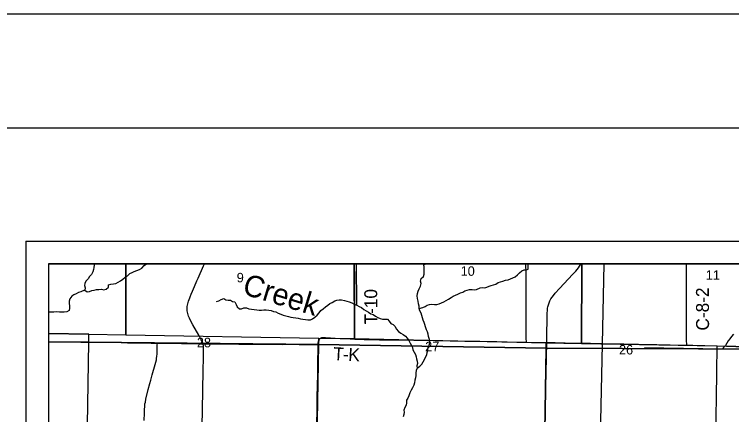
# Model space of a CAD drawing. Extents: x 0 to 42, y 0 to 22.
# Drawn here: x 1.949 to 5.107, y 20.235 to 22 of the extents above; entities that cross this region are included whole.
import ezdxf

# ---------------------------------------------------------------- set-up
doc = ezdxf.new("R2010")
doc.units = 0
for name, color, linetype in [('Default', 7, 'Continuous'), ('GM_X_County_Road', 7, 'Continuous'), ('GM_X_County_Road_Text', 7, 'Continuous'), ('GM_X_Interchange_Ramps', 7, 'Continuous'), ('GM_X_Minor_River', 7, 'Continuous'), ('GM_X_Minor_River_Text', 7, 'Continuous'), ('GM_X_Rail_Line', 7, 'Continuous'), ('GM_X_Section', 7, 'Continuous'), ('GM_X_Section_Text', 7, 'Continuous'), ('GM_X_State_Route', 7, 'Continuous'), ('GM_X_Township_Road', 7, 'Continuous'), ('GM_X_Township_Road_Text', 7, 'Continuous'), ('SH_Border', 7, 'Continuous'), ('SH_Cut_Line', 7, 'Continuous'), ('SH_Data', 7, 'Continuous')]:
    doc.layers.add(name, color=color, linetype=linetype)

msp = doc.modelspace()

# ---------------------------------------------------------------- linework, layer by layer
at = {"layer": 'Default'}
for points in [[(2.4394, 20.9), (2.1, 20.9), (2.1, 20.5927), (2.2765, 20.5898), (2.4394, 20.5869)], [(3.4456, 20.9), (2.4394, 20.9), (2.4394, 20.5869), (3.29, 20.5725), (3.4457, 20.5713)], [(4.4477, 20.9), (3.4456, 20.9), (3.4457, 20.5713), (4.2909, 20.5517), (4.4454, 20.5483)], [(5.4509, 20.9), (4.4477, 20.9), (4.4454, 20.5483), (5.2948, 20.5335), (5.4509, 20.5312)], [(2.1, 20.5927), (2.1, 20.5562), (2.2763, 20.5545), (2.2765, 20.5898)], [(2.1, 20.5562), (2.1, 19.5535), (2.2608, 19.5512), (2.2763, 20.5545)]]:
    msp.add_lwpolyline(points, close=True, dxfattribs=at)
at = {"layer": 'GM_X_County_Road'}
for points in [[(2.7794, 20.5478), (2.7784, 20.5512), (2.7761, 20.5571), (2.7721, 20.5656), (2.7613, 20.5848), (2.7353, 20.6308), (2.7249, 20.6499), (2.7194, 20.661), (2.7158, 20.6695), (2.7138, 20.6753), (2.7122, 20.6813), (2.711, 20.6873), (2.7101, 20.6934), (2.7097, 20.6995), (2.7097, 20.7057), (2.7101, 20.7118), (2.7108, 20.7179), (2.7122, 20.7239), (2.7157, 20.7359), (2.721, 20.7499), (2.7223, 20.7547), (2.7272, 20.7656), (2.7333, 20.7789), (2.7416, 20.7996), (2.7516, 20.8247), (2.7577, 20.8369), (2.782, 20.8912), (2.7843, 20.8971), (2.7856, 20.9)], [(4.9094, 20.5418), (4.9088, 20.5503), (4.9083, 20.5565), (4.9075, 20.6933), (4.9074, 20.768), (4.9083, 20.9)], [(3.2868, 20.5441), (3.2867, 20.5493), (3.2867, 20.551), (3.2868, 20.5536), (3.2873, 20.5566), (3.2881, 20.5598), (3.2891, 20.5629), (3.2905, 20.5658), (3.2923, 20.5685), (3.2936, 20.5698)], [(3.2936, 20.5698), (3.2946, 20.5709), (3.2972, 20.5728), (3.3002, 20.5742), (3.3033, 20.5751), (3.3065, 20.5756), (3.3096, 20.5758), (3.319, 20.5756), (3.3836, 20.5714), (3.4277, 20.5695), (3.4475, 20.5686)], [(3.4475, 20.5686), (3.4649, 20.5679), (3.4772, 20.5678), (3.4832, 20.5675), (3.4889, 20.567), (3.5071, 20.5665), (3.5101, 20.5665), (3.5129, 20.5661), (3.5564, 20.5655), (3.6126, 20.5652), (3.8022, 20.5615), (3.9327, 20.559), (3.9358, 20.559), (3.948, 20.5595), (3.9791, 20.559), (3.9978, 20.5584), (4.0723, 20.5572), (4.1188, 20.5562), (4.2032, 20.5546)], [(2.1, 20.5567), (2.1888, 20.556), (2.2416, 20.5553), (2.3225, 20.5543), (2.4188, 20.5527), (2.4467, 20.5524), (2.4622, 20.5523), (2.4715, 20.5521), (2.4746, 20.552), (2.5055, 20.5515), (2.5506, 20.5507), (2.5786, 20.5503)], [(2.5786, 20.5503), (2.6344, 20.5497), (2.6841, 20.549), (2.7086, 20.5485), (2.7303, 20.5482), (2.7614, 20.548), (2.7794, 20.5478)], [(2.7666, 19.6003), (2.7676, 19.6442), (2.7685, 19.7126), (2.7694, 19.7685), (2.7704, 19.8244), (2.7728, 19.9642), (2.7739, 20.0482), (2.775, 20.1134), (2.7774, 20.2563), (2.7802, 20.4303), (2.7813, 20.4862), (2.7821, 20.5298), (2.7818, 20.5361), (2.7813, 20.5392), (2.7802, 20.5453), (2.7794, 20.5478)], [(2.7794, 20.5478), (2.8203, 20.5475), (2.8603, 20.5471), (2.9372, 20.5462), (3.011, 20.5459), (3.0385, 20.5456), (3.1062, 20.5453), (3.1311, 20.5449), (3.1476, 20.5452), (3.2034, 20.545), (3.2294, 20.5445), (3.2787, 20.5442), (3.2868, 20.5441)], [(4.2032, 20.5546), (4.2742, 20.5532), (4.2927, 20.5531)], [(4.2927, 20.5531), (4.299, 20.5531), (4.3301, 20.5528), (4.3737, 20.5522), (4.4389, 20.5506), (4.4855, 20.5499), (4.5352, 20.5487), (4.5849, 20.548), (4.6316, 20.5472), (4.6968, 20.5465), (4.7776, 20.545), (4.8367, 20.5435), (4.8988, 20.542), (4.9094, 20.5418)], [(4.9094, 20.5418), (4.9361, 20.5413), (5.0418, 20.5382), (5.0427, 20.5382)], [(5.0163, 19.5159), (5.0173, 19.5982), (5.0195, 19.7226), (5.0206, 19.7662), (5.0224, 19.8066), (5.0252, 19.8594), (5.0304, 19.9526), (5.0345, 20.0334), (5.0392, 20.1203), (5.0399, 20.1421), (5.0399, 20.1607), (5.0387, 20.204), (5.0389, 20.2383), (5.0395, 20.3005), (5.0415, 20.4311), (5.0426, 20.5276), (5.0427, 20.5382)], [(5.0427, 20.5382), (5.1257, 20.5362), (5.2872, 20.5311), (5.3432, 20.5304), (5.3991, 20.5296), (5.4507, 20.5283)]]:
    msp.add_lwpolyline(points, dxfattribs=at)
at = {"layer": 'GM_X_Interchange_Ramps'}
msp.add_lwpolyline([(6.4601, 20.9), (2.1, 20.9), (2.1, 18.5138)], dxfattribs=at)
at = {"layer": 'GM_X_Minor_River'}
for p, q in [((3.4562, 20.7176), (3.4557, 20.9)), ((4.2116, 20.8768), (4.2114, 20.9))]:
    msp.add_line(p, q, dxfattribs=at)
for points in [[(2.3019, 20.9), (2.3005, 20.894), (2.2992, 20.8841), (2.2974, 20.8743), (2.2938, 20.8641), (2.289, 20.8536), (2.2804, 20.8439), (2.2733, 20.8334), (2.264, 20.8234), (2.2588, 20.8136), (2.2574, 20.8038), (2.2602, 20.7943), (2.2596, 20.784), (2.2693, 20.7762), (2.28, 20.7779), (2.2895, 20.7818), (2.301, 20.7839), (2.3113, 20.7863), (2.3208, 20.7865), (2.3322, 20.7877), (2.3424, 20.786), (2.3527, 20.7876), (2.3639, 20.7969), (2.3637, 20.8068), (2.3741, 20.8103), (2.3858, 20.8112), (2.3957, 20.8129), (2.4061, 20.8187), (2.4158, 20.825), (2.427, 20.8331), (2.437, 20.8408), (2.447, 20.8467), (2.4575, 20.8567), (2.4671, 20.8614), (2.477, 20.8657), (2.4882, 20.8712), (2.4997, 20.8751), (2.5097, 20.8809), (2.5205, 20.8921), (2.531, 20.8998), (2.5317, 20.9)], [(3.7221, 20.4406), (3.7337, 20.4483), (3.7434, 20.458), (3.7493, 20.4681), (3.7541, 20.4779), (3.7597, 20.4884), (3.7645, 20.4989), (3.7666, 20.5098), (3.7699, 20.52), (3.7709, 20.5306), (3.7749, 20.5412), (3.7778, 20.551), (3.7777, 20.5612), (3.7756, 20.5708), (3.7721, 20.5803), (3.77, 20.5906), (3.7676, 20.6002), (3.7633, 20.6097), (3.759, 20.6216), (3.7558, 20.6323), (3.7527, 20.6419), (3.7491, 20.6522), (3.7459, 20.6625), (3.7431, 20.6725), (3.7392, 20.6832), (3.7345, 20.6931), (3.7317, 20.7031), (3.7304, 20.7137), (3.728, 20.7233), (3.726, 20.7351), (3.7233, 20.7469), (3.7228, 20.7583), (3.7238, 20.7689), (3.7263, 20.7795), (3.7304, 20.79), (3.7375, 20.802), (3.74, 20.8134), (3.7376, 20.824), (3.7401, 20.8346), (3.7499, 20.8446), (3.7531, 20.8544), (3.7534, 20.8651), (3.7532, 20.8753), (3.7527, 20.8848), (3.7518, 20.8955), (3.7568, 20.9)], [(3.7317, 20.7031), (3.7466, 20.7081), (3.757, 20.7116), (3.7666, 20.7171), (3.7765, 20.7203), (3.7868, 20.7216), (3.7981, 20.7202), (3.8084, 20.7203), (3.8198, 20.7239), (3.8298, 20.7275), (3.8402, 20.7322), (3.8498, 20.7384), (3.8602, 20.7439), (3.8717, 20.7512), (3.8814, 20.7574), (3.8913, 20.7618), (3.9017, 20.7665), (3.9124, 20.7719), (3.9228, 20.7755), (3.9328, 20.7813), (3.9423, 20.7838), (3.9526, 20.7862), (3.964, 20.7875), (3.9742, 20.7861), (3.9837, 20.7874), (3.9998, 20.7935), (4.0094, 20.7956), (4.02, 20.7946), (4.0295, 20.7966), (4.0391, 20.801), (4.0486, 20.8046), (4.0582, 20.807), (4.0682, 20.811), (4.0789, 20.8172), (4.0892, 20.8204), (4.0999, 20.8239), (4.111, 20.8275), (4.1228, 20.8295), (4.1336, 20.8342), (4.1435, 20.8385), (4.1535, 20.8432), (4.1636, 20.8513), (4.1733, 20.861), (4.183, 20.8695), (4.1929, 20.8731), (4.2036, 20.874), (4.2116, 20.8768)], [(2.2596, 20.784), (2.2482, 20.7801), (2.2412, 20.7761), (2.2313, 20.7729), (2.2209, 20.7682), (2.2113, 20.7635), (2.2013, 20.7569), (2.1935, 20.746), (2.1909, 20.7351), (2.1899, 20.7252), (2.1912, 20.7153), (2.1913, 20.7043), (2.1896, 20.6945), (2.1796, 20.6879), (2.1682, 20.6874), (2.1575, 20.6865), (2.1473, 20.6874), (2.1325, 20.6885), (2.1226, 20.6876), (2.1124, 20.6867), (2.1018, 20.6866), (2.1, 20.6864)], [(2.8385, 20.7336), (2.8489, 20.7368), (2.86, 20.7433), (2.8707, 20.7465), (2.8805, 20.7414), (2.8907, 20.7392), (2.9001, 20.7394), (2.9099, 20.7343), (2.9201, 20.7321), (2.9255, 20.7214), (2.9298, 20.711), (2.9395, 20.7021), (2.949, 20.7023), (2.9593, 20.7066), (2.9703, 20.706), (2.9812, 20.7019), (2.9937, 20.7001), (3.0043, 20.6984), (3.0171, 20.697), (3.0273, 20.6956), (3.0372, 20.6954), (3.0471, 20.6974), (3.0574, 20.6972), (3.0687, 20.6954), (3.0797, 20.6937), (3.0894, 20.6904), (3.1, 20.6883), (3.1098, 20.6831), (3.1218, 20.6787), (3.1331, 20.6743), (3.1448, 20.6706), (3.1557, 20.6673), (3.1659, 20.6648), (3.1768, 20.6634), (3.1878, 20.6613), (3.1984, 20.661), (3.2086, 20.6578), (3.2191, 20.6557), (3.2301, 20.655), (3.2403, 20.6533), (3.2521, 20.6534), (3.262, 20.657), (3.2717, 20.6647), (3.2814, 20.6744), (3.2915, 20.6837), (3.2982, 20.6945), (3.3079, 20.7023), (3.3183, 20.71), (3.3284, 20.7178), (3.338, 20.7251), (3.348, 20.7302), (3.3592, 20.7372), (3.3691, 20.74), (3.3794, 20.7413), (3.3896, 20.7418), (3.4017, 20.7389), (3.4122, 20.7349), (3.4236, 20.732), (3.4348, 20.7275), (3.4453, 20.7227), (3.4562, 20.7176), (3.4667, 20.7113), (3.4772, 20.7069), (3.488, 20.699), (3.4981, 20.6935), (3.5086, 20.6868), (3.5183, 20.6801), (3.5281, 20.6761), (3.5386, 20.6698), (3.5498, 20.6635), (3.5596, 20.6587), (3.5701, 20.6554), (3.5804, 20.656), (3.591, 20.6565), (3.5991, 20.6468), (3.6061, 20.6368), (3.6162, 20.6331), (3.6255, 20.6231), (3.6294, 20.6131), (3.6402, 20.6019), (3.6502, 20.594), (3.6603, 20.5885), (3.6704, 20.5815), (3.6785, 20.5718), (3.6863, 20.5614), (3.6909, 20.5502), (3.6968, 20.5402), (3.7022, 20.5306), (3.7035, 20.5211), (3.7097, 20.5111), (3.7144, 20.5008), (3.7183, 20.4904), (3.7189, 20.4805), (3.7228, 20.4702), (3.7241, 20.4607), (3.7212, 20.4509), (3.7221, 20.4406), (3.718, 20.4297), (3.717, 20.4195), (3.7171, 20.4077), (3.7146, 20.3975)], [(5.1147, 20.5905), (5.1065, 20.5801), (5.099, 20.57), (5.0916, 20.5603), (5.0853, 20.5502), (5.0794, 20.5405), (5.0715, 20.5308), (5.0668, 20.5233)], [(5.0668, 20.5233), (4.7236, 20.5298)], [(3.7146, 20.3975), (3.7117, 20.3866), (3.7099, 20.3748), (3.7074, 20.3646), (3.7018, 20.3534), (3.6966, 20.3429), (3.6907, 20.3308), (3.6854, 20.3181), (3.681, 20.3083), (3.6751, 20.2985), (3.6752, 20.2879), (3.6746, 20.2769), (3.6675, 20.2664), (3.6639, 20.2555), (3.6644, 20.2453), (3.6634, 20.2354), (3.6609, 20.2252)]]:
    msp.add_lwpolyline(points, dxfattribs=at)
at = {"layer": 'GM_X_Rail_Line'}
msp.add_lwpolyline([(4.4201, 14.1), (4.4258, 14.4841), (4.4505, 15.4825), (4.4609, 16.2603), (4.4628, 16.4862), (4.4739, 16.927), (4.4741, 16.9438), (4.4795, 17.4845), (4.5072, 18.7551), (4.5183, 19.5978), (4.5387, 20.5461), (4.5449, 20.9)], dxfattribs=at)
at = {"layer": 'GM_X_Section'}
for points in [[(2.2765, 20.5898), (2.4394, 20.5869), (3.29, 20.5725), (3.2881, 20.5445), (2.2763, 20.5545)], [(3.29, 20.5725), (3.4457, 20.5713), (4.2909, 20.5517), (4.2905, 20.5288), (3.2881, 20.5445)], [(2.2763, 20.5545), (3.2881, 20.5445), (3.2701, 19.5386), (2.2608, 19.5512)], [(3.2881, 20.5445), (4.2905, 20.5288), (4.2741, 19.5242), (3.2701, 19.5386)], [(4.2905, 20.5288), (5.2947, 20.5242), (5.2809, 19.5139), (5.2739, 19.514), (4.2741, 19.5242)], [(4.2909, 20.5517), (4.4454, 20.5483), (5.2948, 20.5335), (5.2947, 20.5242), (4.2905, 20.5288)]]:
    msp.add_lwpolyline(points, close=True, dxfattribs=at)
at = {"layer": 'GM_X_State_Route'}
msp.add_lwpolyline([(4.2845, 20.1404), (4.2874, 20.2896), (4.2927, 20.5531), (4.293, 20.564), (4.2952, 20.6821), (4.2958, 20.6946), (4.2968, 20.7039), (4.2978, 20.7101), (4.3, 20.7192), (4.3029, 20.7282), (4.3067, 20.7368), (4.3113, 20.745), (4.3164, 20.7529), (4.3221, 20.7604), (4.3301, 20.77), (4.3488, 20.7908), (4.4079, 20.8547), (4.4206, 20.8683), (4.4267, 20.8754), (4.4324, 20.8827), (4.4375, 20.8904), (4.4421, 20.8984), (4.4429, 20.9)], dxfattribs=at)
at = {"layer": 'GM_X_Township_Road'}
for points in [[(3.4475, 20.5686), (3.4476, 20.5761), (3.4482, 20.6134), (3.4485, 20.6942), (3.4475, 20.7719), (3.4472, 20.8341), (3.4471, 20.9)], [(4.2032, 20.5546), (4.203, 20.5598), (4.2029, 20.566), (4.2024, 20.6157), (4.2025, 20.6901), (4.2022, 20.7646), (4.2017, 20.8577), (4.2011, 20.9)], [(3.2868, 20.5441), (3.2867, 20.5493), (3.2867, 20.551), (3.2868, 20.5536), (3.2873, 20.5566), (3.2881, 20.5598), (3.2891, 20.5629), (3.2905, 20.5658), (3.2923, 20.5685), (3.2936, 20.5698)], [(3.2936, 20.5698), (3.2946, 20.5709), (3.2972, 20.5728), (3.3002, 20.5742), (3.3033, 20.5751), (3.3065, 20.5756), (3.3096, 20.5758), (3.319, 20.5756), (3.3836, 20.5714), (3.4277, 20.5695), (3.4475, 20.5686)], [(3.4475, 20.5686), (3.4649, 20.5679), (3.4772, 20.5678), (3.4832, 20.5675), (3.4889, 20.567), (3.5071, 20.5665), (3.5101, 20.5665), (3.5129, 20.5661), (3.5564, 20.5655), (3.6126, 20.5652), (3.8022, 20.5615), (3.9327, 20.559), (3.9358, 20.559), (3.948, 20.5595), (3.9791, 20.559), (3.9978, 20.5584), (4.0723, 20.5572), (4.1188, 20.5562), (4.2032, 20.5546)], [(2.1, 20.5567), (2.1888, 20.556), (2.2416, 20.5553), (2.3225, 20.5543), (2.4188, 20.5527), (2.4467, 20.5524), (2.4622, 20.5523), (2.4715, 20.5521), (2.4746, 20.552), (2.5055, 20.5515), (2.5506, 20.5507), (2.5786, 20.5503)], [(2.521, 20.2094), (2.522, 20.2422), (2.5225, 20.2604), (2.5228, 20.2679), (2.5231, 20.2756), (2.524, 20.2828), (2.526, 20.2908), (2.5285, 20.3031), (2.5386, 20.3454), (2.5455, 20.3724), (2.5496, 20.3871), (2.5561, 20.4108), (2.5688, 20.4556), (2.5743, 20.4767), (2.5754, 20.4828), (2.5765, 20.4922), (2.5771, 20.5015), (2.5776, 20.5202), (2.5783, 20.5419), (2.5786, 20.5503)], [(2.5786, 20.5503), (2.6344, 20.5497), (2.6841, 20.549), (2.7086, 20.5485), (2.7303, 20.5482), (2.7614, 20.548), (2.7794, 20.5478)], [(2.7794, 20.5478), (2.8203, 20.5475), (2.8603, 20.5471), (2.9372, 20.5462), (3.011, 20.5459), (3.0385, 20.5456), (3.1062, 20.5453), (3.1311, 20.5449), (3.1476, 20.5452), (3.2034, 20.545), (3.2294, 20.5445), (3.2787, 20.5442), (3.2868, 20.5441)], [(3.2733, 19.7638), (3.2734, 19.7731), (3.275, 19.882), (3.277, 20.0126), (3.2822, 20.2673), (3.2828, 20.3171), (3.2838, 20.3606), (3.2847, 20.4166), (3.2854, 20.4508), (3.2868, 20.5441)], [(4.2032, 20.5546), (4.2742, 20.5532), (4.2927, 20.5531)], [(4.2927, 20.5531), (4.299, 20.5531), (4.3301, 20.5528), (4.3737, 20.5522), (4.4389, 20.5506), (4.4855, 20.5499), (4.5352, 20.5487), (4.5849, 20.548), (4.6316, 20.5472), (4.6968, 20.5465), (4.7776, 20.545), (4.8367, 20.5435), (4.8988, 20.542), (4.9094, 20.5418)]]:
    msp.add_lwpolyline(points, dxfattribs=at)
at = {"layer": 'SH_Border'}
msp.add_lwpolyline([(1.5, 21.5), (33.5, 21.5), (33.5, 0.5), (1.5, 0.5)], close=True, dxfattribs=at)
at = {"layer": 'SH_Cut_Line'}
msp.add_lwpolyline([(0, 0), (34, 0), (34, 22), (0, 22)], close=True, dxfattribs=at)
at = {"layer": 'SH_Data'}
for p, q in [((2, 21), (9, 21)), ((2, 21), (2, 14)), ((2.1, 20.9), (2.1, 14.1)), ((2.1, 20.9), (8.9, 20.9))]:
    msp.add_line(p, q, dxfattribs=at)

# ---------------------------------------------------------------- texts
at = {"layer": 'GM_X_County_Road_Text'}
msp.add_text('C-8-2', height=0.05682, rotation=90.2952, dxfattribs=at).set_placement((5.0074, 20.6059))
at = {"layer": 'GM_X_Minor_River_Text'}
msp.add_text('Creek', height=0.09476, rotation=343.0229, dxfattribs=at).set_placement((2.9481, 20.7685))
at = {"layer": 'GM_X_Section_Text'}
for s, height, p in [('10', 0.04186, (3.9137, 20.8471)), ('9', 0.0419, (2.9279, 20.8183)), ('11', 0.04186, (4.9929, 20.8296)), ('28', 0.04186, (2.7525, 20.5321)), ('27', 0.04186, (3.7575, 20.5146)), ('26', 0.04186, (4.6108, 20.5004))]:
    msp.add_text(s, height=height, rotation=0, dxfattribs=at).set_placement(p)
at = {"layer": 'GM_X_Township_Road_Text'}
for s, height, rotation, p in [('T-10', 0.05682, 90.3537, (3.5473, 20.6329)), ('T', 0.0568, 356.8958, (3.3517, 20.4762)), ('K', 0.0568, 357.2924, (3.4179, 20.4726)), ('-', 0.0568, 356.9308, (3.3942, 20.4739))]:
    msp.add_text(s, height=height, rotation=rotation, dxfattribs=at).set_placement(p)

doc.saveas('drawing.dxf')
